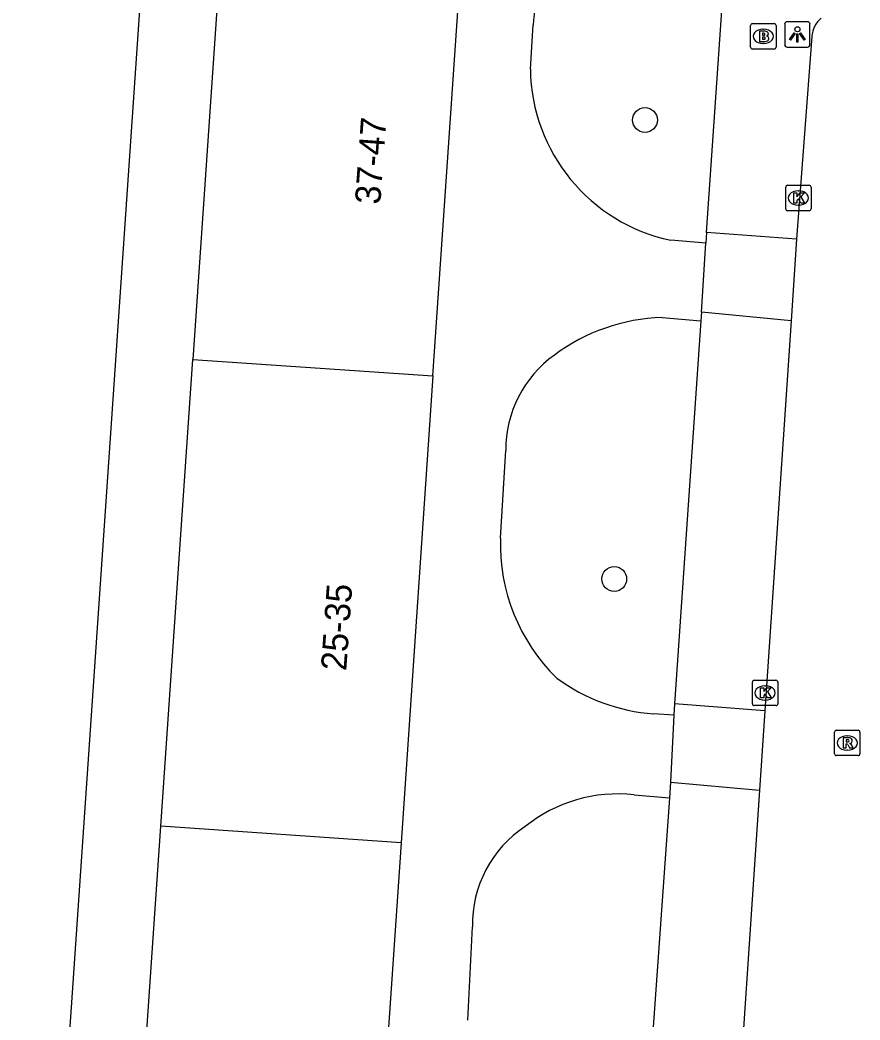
# Model space of a CAD drawing. Extents: x 161848 to 162726, y 385382 to 386521.
# Drawn here: x 162025.39 to 162058.44, y 385422.49 to 385461.84 of the extents above; entities that cross this region are included whole.
import ezdxf

# ---------------------------------------------------------------- set-up
doc = ezdxf.new("R2010")
doc.units = 0
for name, color, linetype in [('IMGEO_Boom', 7, 'Continuous'), ('IMGEO_Brandkraan', 7, 'Continuous'), ('IMGEO_Kolk', 7, 'Continuous'), ('IMGEO_Lichtpunt', 7, 'Continuous'), ('IMGEO_Pand', 7, 'Continuous'), ('IMGEO_Pand_nummerreeks', 7, 'Continuous'), ('IMGEO_Rijbaan_lokaal_open', 7, 'Continuous'), ('IMGEO_Rioolput', 7, 'Continuous'), ('IMGEO_Voetpad_open', 7, 'Continuous')]:
    doc.layers.add(name, color=color, linetype=linetype)

msp = doc.modelspace()

# ---------------------------------------------------------------- linework, layer by layer
at = {"layer": 'IMGEO_Boom'}
for centre in [(162049.979, 385457.9), (162048.767, 385439.84)]:
    msp.add_circle(centre, 0.489, dxfattribs=at)
at = {"layer": 'IMGEO_Brandkraan'}
for p, q in [((162054.132, 385460.766), (162054.132, 385461.618)), ((162054.207, 385461.692), (162055.059, 385461.692)), ((162054.62, 385461.472), (162054.645, 385461.472)), ((162055.133, 385461.618), (162055.133, 385460.766)), ((162055.059, 385460.692), (162054.207, 385460.692)), ((162054.643, 385460.912), (162054.618, 385460.912))]:
    msp.add_line(p, q, dxfattribs=at)
for points in [[(162054.132, 385460.766), (162054.132, 385461.618)], [(162054.207, 385461.692), (162055.059, 385461.692)], [(162054.48, 385461.392), (162054.48, 385460.992), (162054.693, 385460.992)], [(162054.711, 385461.392), (162054.48, 385461.392)], [(162055.133, 385461.618), (162055.133, 385460.766)], [(162054.659, 385461.311), (162054.605, 385461.311), (162054.605, 385461.235)], [(162054.605, 385461.235), (162054.658, 385461.235)], [(162054.667, 385461.159), (162054.605, 385461.159), (162054.605, 385461.078)], [(162054.605, 385461.078), (162054.667, 385461.078)], [(162055.059, 385460.692), (162054.207, 385460.692)]]:
    msp.add_lwpolyline(points, dxfattribs=at)
for centre, radius, start, end in [((162054.209, 385461.616), 0.0765, 91.552, 178.448), ((162054.209, 385461.616), 0.0765, 91.552, 178.448), ((162054.715, 385461.247), 0.145, 59.4692, 91.5367), ((162054.74, 385461.294), 0.0922, 285.5137, 58.1501), ((162055.057, 385461.616), 0.0765, 1.552, 88.448), ((162055.057, 385461.616), 0.0765, 1.552, 88.448), ((162054.66, 385461.273), 0.0379, 267.8285, 90.9355), ((162054.668, 385461.118), 0.0404, 269.8759, 90.5077), ((162054.699, 385461.243), 0.251, 268.6676, 293.5347), ((162054.745, 385461.102), 0.105, 301.3115, 78.989), ((162054.209, 385460.768), 0.0765, 181.552, 268.448), ((162054.209, 385460.768), 0.0765, 181.552, 268.448), ((162055.057, 385460.768), 0.0765, 271.552, 358.448), ((162055.057, 385460.768), 0.0765, 271.552, 358.448)]:
    msp.add_arc(centre, radius, start, end, dxfattribs=at)
for centre, major_axis, ratio, start_param, end_param in [((162054.619, 385461.192), (-0.387, 0.002), 0.722429, 4.712389, 7.853982), ((162054.644, 385461.192), (-0.39, 0.002), 0.717154, 1.570796, 4.712389)]:
    msp.add_ellipse(centre, major_axis=major_axis, ratio=ratio, start_param=start_param, end_param=end_param, dxfattribs=at)
at = {"layer": 'IMGEO_Kolk'}
for p, q in [((162055.513, 385454.404), (162055.513, 385455.256)), ((162055.588, 385455.33), (162056.44, 385455.33)), ((162056.001, 385455.11), (162056.026, 385455.11)), ((162056.514, 385455.256), (162056.514, 385454.404)), ((162056.44, 385454.33), (162055.588, 385454.33)), ((162056.024, 385454.55), (162055.999, 385454.55)), ((162054.203, 385434.931), (162054.203, 385435.783)), ((162054.278, 385435.857), (162055.13, 385435.857)), ((162055.204, 385435.783), (162055.204, 385434.931)), ((162054.691, 385435.637), (162054.716, 385435.637)), ((162054.714, 385435.077), (162054.689, 385435.077)), ((162055.13, 385434.857), (162054.278, 385434.857))]:
    msp.add_line(p, q, dxfattribs=at)
for points in [[(162055.513, 385454.404), (162055.513, 385455.256)], [(162055.588, 385455.33), (162056.44, 385455.33)], [(162056.514, 385455.256), (162056.514, 385454.404)], [(162055.834, 385455.03), (162055.957, 385455.03), (162055.957, 385454.879), (162056.087, 385455.03), (162056.251, 385455.03), (162056.105, 385454.879), (162056.258, 385454.63), (162056.106, 385454.63), (162056.021, 385454.794), (162055.957, 385454.727), (162055.957, 385454.63), (162055.834, 385454.63), (162055.834, 385455.03)], [(162056.44, 385454.33), (162055.588, 385454.33)], [(162054.203, 385434.931), (162054.203, 385435.783)], [(162054.278, 385435.857), (162055.13, 385435.857)], [(162055.204, 385435.783), (162055.204, 385434.931)], [(162054.524, 385435.557), (162054.647, 385435.557), (162054.647, 385435.406), (162054.777, 385435.557), (162054.941, 385435.557), (162054.795, 385435.406), (162054.948, 385435.157), (162054.796, 385435.157), (162054.711, 385435.321), (162054.647, 385435.254), (162054.647, 385435.157), (162054.524, 385435.157), (162054.524, 385435.557)], [(162055.13, 385434.857), (162054.278, 385434.857)]]:
    msp.add_lwpolyline(points, dxfattribs=at)
for centre, start, end in [((162055.59, 385455.254), 91.552, 178.448), ((162055.59, 385455.254), 91.552, 178.448), ((162056.438, 385455.254), 1.552, 88.448), ((162056.438, 385455.254), 1.552, 88.448), ((162055.59, 385454.406), 181.552, 268.448), ((162055.59, 385454.406), 181.552, 268.448), ((162056.438, 385454.406), 271.552, 358.448), ((162056.438, 385454.406), 271.552, 358.448), ((162054.28, 385435.781), 91.552, 178.448), ((162054.28, 385435.781), 91.552, 178.448), ((162055.128, 385435.781), 1.552, 88.448), ((162055.128, 385435.781), 1.552, 88.448), ((162054.28, 385434.933), 181.552, 268.448), ((162054.28, 385434.933), 181.552, 268.448), ((162055.128, 385434.933), 271.552, 358.448), ((162055.128, 385434.933), 271.552, 358.448)]:
    msp.add_arc(centre, 0.0765, start, end, dxfattribs=at)
for centre, major_axis, ratio, start_param, end_param in [((162056, 385454.83), (-0.387, 0.002), 0.722429, 4.712389, 7.853982), ((162056.025, 385454.83), (-0.39, 0.002), 0.717154, 1.570796, 4.712389), ((162054.69, 385435.357), (-0.387, 0.002), 0.722429, 4.712389, 7.853982), ((162054.715, 385435.357), (-0.39, 0.002), 0.717154, 1.570796, 4.712389)]:
    msp.add_ellipse(centre, major_axis=major_axis, ratio=ratio, start_param=start_param, end_param=end_param, dxfattribs=at)
at = {"layer": 'IMGEO_Lichtpunt'}
for p, q in [((162056.375, 385461.766), (162055.567, 385461.766)), ((162056.375, 385461.766), (162055.567, 385461.766)), ((162055.473, 385461.671), (162055.473, 385460.864)), ((162055.473, 385461.671), (162055.473, 385460.864)), ((162056.469, 385460.864), (162056.469, 385461.671)), ((162056.469, 385460.864), (162056.469, 385461.671)), ((162055.567, 385460.77), (162056.375, 385460.77)), ((162055.567, 385460.77), (162056.375, 385460.77))]:
    msp.add_line(p, q, dxfattribs=at)
for points in [[(162055.847, 385461.335), (162055.886, 385461.307), (162055.698, 385461.045), (162055.66, 385461.072), (162055.847, 385461.335)], [(162055.949, 385461.287), (162055.996, 385461.287), (162055.996, 385460.965), (162055.949, 385460.965), (162055.949, 385461.287)], [(162056.059, 385461.307), (162056.097, 385461.334), (162056.284, 385461.072), (162056.245, 385461.044), (162056.059, 385461.307)]]:
    msp.add_lwpolyline(points, dxfattribs=at)
msp.add_circle((162055.972, 385461.469), 0.0994, dxfattribs=at)
for centre, start, end in [((162055.567, 385461.671), 90, 180), ((162055.567, 385461.671), 90, 180), ((162056.375, 385461.671), 0, 90), ((162056.375, 385461.671), 0, 90), ((162055.567, 385460.864), 180, 270), ((162055.567, 385460.864), 180, 270), ((162056.375, 385460.864), 270, 0), ((162056.375, 385460.864), 270, 360)]:
    msp.add_arc(centre, 0.0946, start, end, dxfattribs=at)
at = {"layer": 'IMGEO_Pand'}
for points in [[(162033.453, 385466.849), (162032.195, 385448.479)], [(162041.634, 385447.833), (162042.889, 385466.204)], [(162030.936, 385430.108), (162032.195, 385448.479)], [(162032.195, 385448.479), (162041.634, 385447.833)], [(162041.634, 385447.833), (162040.379, 385429.463)], [(162029.678, 385411.738), (162030.936, 385430.108)], [(162040.379, 385429.463), (162030.936, 385430.108)], [(162040.379, 385429.463), (162039.123, 385411.092)]]:
    msp.add_lwpolyline(points, dxfattribs=at)
at = {"layer": 'IMGEO_Rijbaan_lokaal_open'}
for points in [[(162056.541, 385461.189), (162055.943, 385453.209)], [(162055.943, 385453.209), (162055.727, 385449.995)], [(162055.727, 385449.995), (162054.696, 385434.648)], [(162054.696, 385434.648), (162054.486, 385431.526)], [(162054.486, 385431.526), (162053.449, 385416.102)]]:
    msp.add_lwpolyline(points, dxfattribs=at)
msp.add_arc((162057.552, 385461.119), 1.013, 129.224, 176.0544, dxfattribs=at)
at = {"layer": 'IMGEO_Rioolput'}
for p, q in [((162057.435, 385432.963), (162057.435, 385433.815)), ((162057.51, 385433.889), (162058.362, 385433.889)), ((162058.436, 385433.815), (162058.436, 385432.963)), ((162057.923, 385433.669), (162057.948, 385433.669)), ((162057.946, 385433.109), (162057.921, 385433.109)), ((162058.362, 385432.889), (162057.51, 385432.889))]:
    msp.add_line(p, q, dxfattribs=at)
for points in [[(162057.435, 385432.963), (162057.435, 385433.815)], [(162057.51, 385433.889), (162058.362, 385433.889)], [(162058.436, 385433.815), (162058.436, 385432.963)], [(162058.024, 385433.587), (162057.772, 385433.589), (162057.772, 385433.189)], [(162057.95, 385433.508), (162057.896, 385433.508), (162057.896, 385433.427)], [(162057.896, 385433.427), (162057.948, 385433.427)], [(162057.772, 385433.189), (162057.896, 385433.189), (162057.896, 385433.351), (162057.907, 385433.351)], [(162057.954, 385433.322), (162058.025, 385433.189), (162058.165, 385433.189), (162058.1, 385433.315)], [(162058.362, 385432.889), (162057.51, 385432.889)]]:
    msp.add_lwpolyline(points, dxfattribs=at)
for centre, radius, start, end in [((162057.512, 385433.813), 0.0765, 91.552, 178.448), ((162057.512, 385433.813), 0.0765, 91.552, 178.448), ((162058.36, 385433.813), 0.0765, 1.552, 88.448), ((162058.36, 385433.813), 0.0765, 1.552, 88.448), ((162057.932, 385433.616), 0.19, 274.7715, 282.9687), ((162057.956, 385433.412), 0.0964, 77.0061, 93.1865), ((162057.97, 385433.469), 0.0378, 276.6634, 79.6772), ((162058.023, 385433.477), 0.109, 350.3612, 89.416), ((162058.021, 385433.477), 0.112, 277.5842, 350.9817), ((162057.906, 385433.298), 0.0533, 26.0293, 88.6989), ((162058.005, 385433.262), 0.108, 29.5134, 73.7905), ((162057.512, 385432.965), 0.0765, 181.552, 268.448), ((162057.512, 385432.965), 0.0765, 181.552, 268.448), ((162058.36, 385432.965), 0.0765, 271.552, 358.448), ((162058.36, 385432.965), 0.0765, 271.552, 358.448)]:
    msp.add_arc(centre, radius, start, end, dxfattribs=at)
for centre, major_axis, ratio, start_param, end_param in [((162057.922, 385433.389), (-0.387, 0.002), 0.722429, 4.712389, 7.853982), ((162057.947, 385433.389), (-0.39, 0.002), 0.717154, 1.570796, 4.712389)]:
    msp.add_ellipse(centre, major_axis=major_axis, ratio=ratio, start_param=start_param, end_param=end_param, dxfattribs=at)
at = {"layer": 'IMGEO_Voetpad_open'}
for points in [[(162052.401, 385453.469), (162053.357, 385467.34)], [(162025.39, 385393.505), (162030.286, 385464.925)], [(162045.469, 385459.895), (162045.573, 385461.643)], [(162052.374, 385453.052), (162050.995, 385453.169)], [(162052.401, 385453.469), (162052.374, 385453.052)], [(162055.943, 385453.209), (162052.401, 385453.469)], [(162052.198, 385450.333), (162052.374, 385453.052)], [(162050.652, 385450.128), (162052.175, 385449.994)], [(162052.175, 385449.994), (162051.134, 385434.922)], [(162052.198, 385450.333), (162052.175, 385449.994)], [(162055.727, 385449.995), (162052.198, 385450.333)], [(162044.292, 385441.443), (162044.498, 385444.89)], [(162051.134, 385434.922), (162051.112, 385434.479)], [(162054.696, 385434.648), (162051.134, 385434.922)], [(162051.112, 385434.479), (162050.318, 385434.533)], [(162051.112, 385434.479), (162050.979, 385431.844)], [(162050.979, 385431.844), (162050.936, 385431.233)], [(162050.979, 385431.844), (162054.486, 385431.526)], [(162049.546, 385431.343), (162050.936, 385431.233)], [(162050.936, 385431.233), (162049.886, 385416.314)], [(162043.002, 385422.486), (162043.191, 385426.153)]]:
    msp.add_lwpolyline(points, dxfattribs=at)
for centre, radius, start, end in [((162051.693, 385461.277), 6.131, 87.5008, 176.5796), ((162052.435, 385459.986), 6.967, 180.7446, 258.0676), ((162050.895, 385442.607), 7.525, 91.8538, 126.5504), ((162049.085, 385444.923), 4.587, 125.609, 180.4112), ((162051.602, 385441.193), 7.314, 178.0386, 225.8799), ((162050.831, 385441.769), 7.254, 233.442, 265.948), ((162048.893, 385425.618), 5.762, 83.4963, 129.0159), ((162047.778, 385426.256), 4.588, 123.1937, 181.2832)]:
    msp.add_arc(centre, radius, start, end, dxfattribs=at)

# ---------------------------------------------------------------- texts
at = {"layer": 'IMGEO_Pand_nummerreeks'}
for s, rotation, p in [('37-47', 85.8505, (162039.561, 385454.557)), ('25-35', 85.9702, (162038.224, 385436.205))]:
    msp.add_text(s, height=1, rotation=rotation, dxfattribs=at).set_placement(p)

doc.saveas('drawing.dxf')
